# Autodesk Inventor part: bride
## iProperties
Created: 2002-03
Part Number: bride
Material: Par défaut
Document SubType Name: Modélisation
Designer: User
Control State: 0
Master: False
Checked Out: False
Shininess: 20.0
Length Units: 11269
Angle Units: 11279
Time Units: 11290
Mass Units: 11283
Length Display Precision: 3
Angle Display Precision: 2
Density: 0.0
Volumn: 0.0
Area: 0.0
PropertySet Name: Model Information
Author: User
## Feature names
1. Extrusion1
2. Extrusion2
3. Extrusion3
4. Réseau circulaire1 [Circular Pattern]
5. Symétrie1 [Mirror]
6. Symétrie2 [Mirror]
